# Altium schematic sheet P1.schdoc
size 297 x 209 mm; Symbol: Drawing-Symbol_A4; @Project Name: New Project_2025-09-22_16-04-54; @Page Count: 2; @Update Date: 2025-10-16; @Create Date: 2025-09-22; @Schematic Name: Schematic1; @Page No: 1; @Page Name: P1; Company: EasyEDA.com; Version: V1.0; Page Size: A4; @Create Time: 16:05:01; @Update Time: 22:39:59; Border: 1; Width: 1170; Height: 825; Region Start: 1; X Region Count: 6; Y Region Count: 4; Blade Width: 10; Title Block Position: 3; @Board Name: Board1; Device: Drawing-Symbol_A4
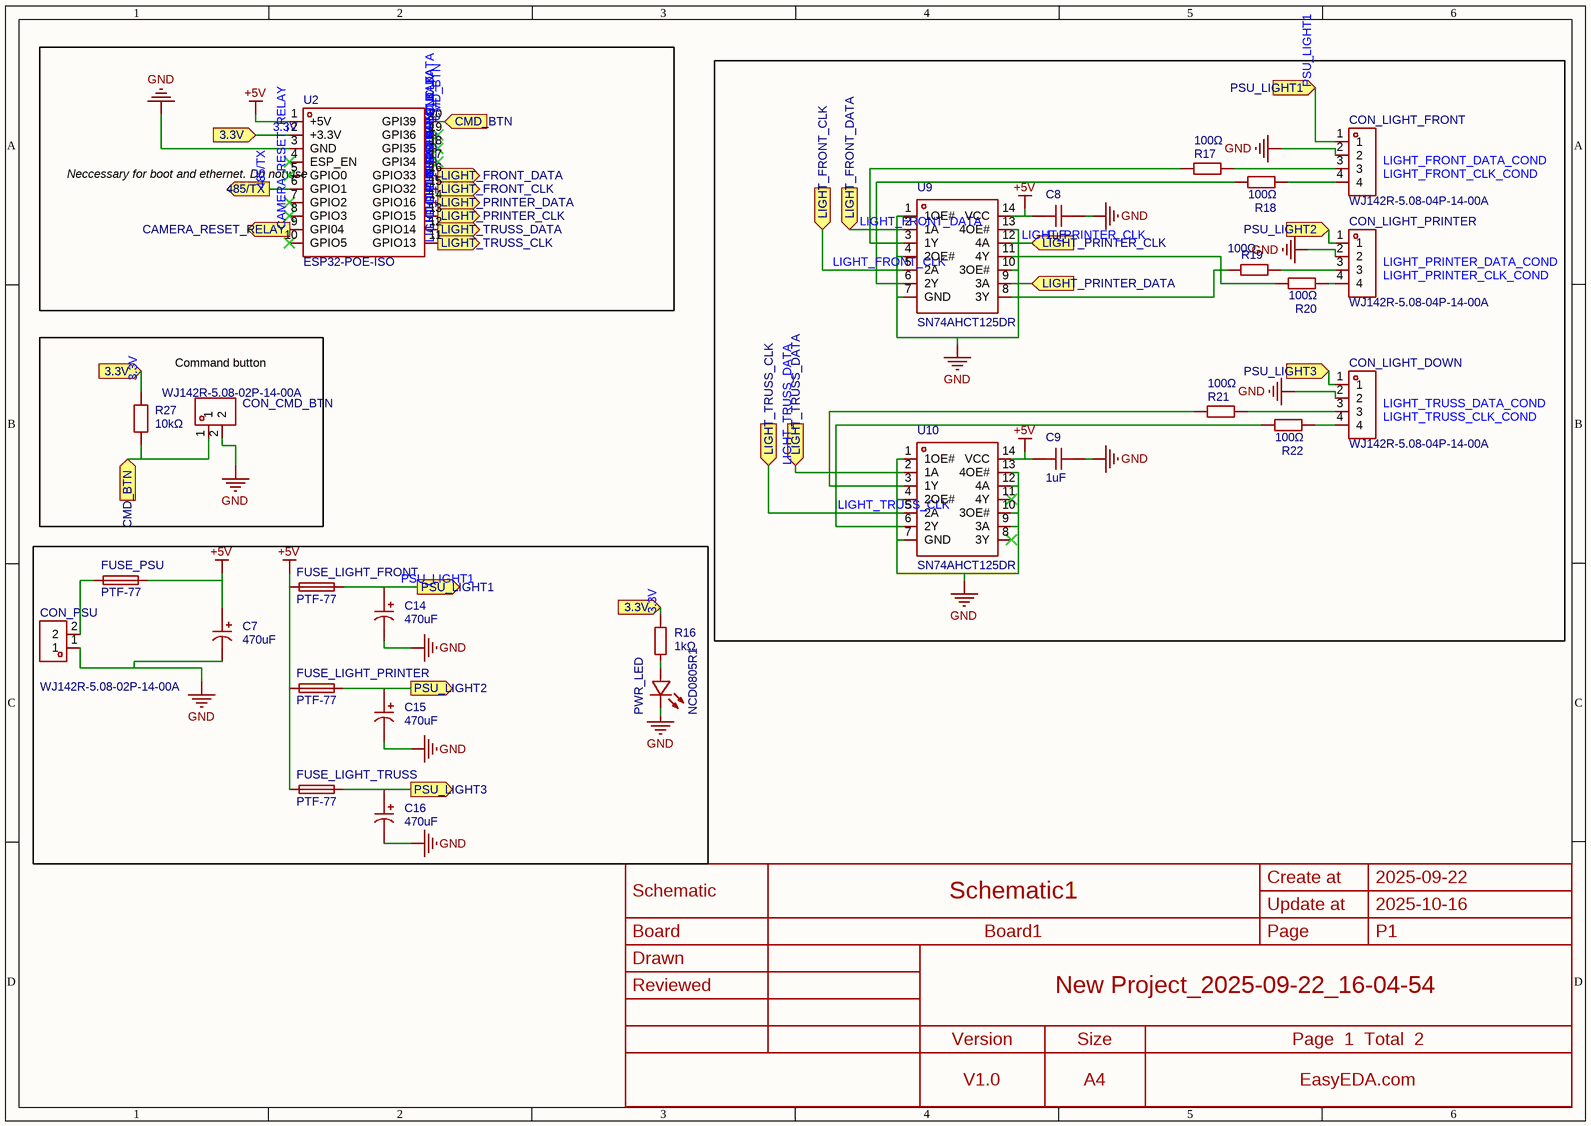
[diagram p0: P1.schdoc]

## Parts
C7  470uF  [CAP-TH_BD8.0-P3.50-D0.5-FD]
C8  1uF  [C0603]
C9  1uF  [C0603]
C14  470uF  [CAP-TH_BD8.0-P3.50-D0.5-FD]
C15  470uF  [CAP-TH_BD8.0-P3.50-D0.5-FD]
C16  470uF  [CAP-TH_BD8.0-P3.50-D0.5-FD]
CON_CMD_BTN  WJ142R-5.08-02P-14-00A  [CONN-TH_2P-P5.08_WJ142R-5.08-2P]
CON_LIGHT_DOWN  WJ142R-5.08-04P-14-00A  [CONN-TH_WJ142R-5.08-4P]
CON_LIGHT_FRONT  WJ142R-5.08-04P-14-00A  [CONN-TH_WJ142R-5.08-4P]
CON_LIGHT_PRINTER  WJ142R-5.08-04P-14-00A  [CONN-TH_WJ142R-5.08-4P]
CON_PSU  WJ142R-5.08-02P-14-00A  [CONN-TH_2P-P5.08_WJ142R-5.08-2P]
FUSE_LIGHT_FRONT  PTF-77  [FUSE-TH_L24.4-W9.4-P22.60]
FUSE_LIGHT_PRINTER  PTF-77  [FUSE-TH_L24.4-W9.4-P22.60]
FUSE_LIGHT_TRUSS  PTF-77  [FUSE-TH_L24.4-W9.4-P22.60]
FUSE_PSU  PTF-77  [FUSE-TH_L24.4-W9.4-P22.60]
PWR_LED  NCD0805R1  [LED0805-R-RD]
R16  1kΩ  [R0603]
R17  100Ω  [R0603]
R18  100Ω  [R0603]
R19  100Ω  [R0603]
R20  100Ω  [R0603]
R21  100Ω  [R0603]
R22  100Ω  [R0603]
R27  10kΩ  [R0603]
U2  ESP32-POE-ISO  [COMM-TH_20P-P2.54_ESP32-POE-ISO]
U9  SN74AHCT125DR  [SOIC-14_L8.7-W3.9-P1.27-LS6.0-BL]
U10  SN74AHCT125DR  [SOIC-14_L8.7-W3.9-P1.27-LS6.0-BL]

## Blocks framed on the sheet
Neccessary for boot and ethernet. Do not use: U2
Command button: CON_CMD_BTN R27

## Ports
3.3V (in), 485/TX (out), CAMERA_RESET_RELAY (out), CMD_BTN (in), LIGHT_FRONT_CLK (in), LIGHT_FRONT_CLK (out), LIGHT_FRONT_DATA (in), LIGHT_FRONT_DATA (out), LIGHT_PRINTER_CLK (in), LIGHT_PRINTER_CLK (out), LIGHT_PRINTER_DATA (in), LIGHT_PRINTER_DATA (out), LIGHT_TRUSS_CLK (in), LIGHT_TRUSS_CLK (out), LIGHT_TRUSS_DATA (in), LIGHT_TRUSS_DATA (out), PSU_LIGHT1 (in), PSU_LIGHT1 (out), PSU_LIGHT2 (in), PSU_LIGHT2 (out), PSU_LIGHT3 (in), PSU_LIGHT3 (out)

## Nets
+5V: C7.1 C8.1 C9.1 FUSE_LIGHT_FRONT.1 FUSE_LIGHT_PRINTER.1 FUSE_LIGHT_TRUSS.1 FUSE_PSU.2 U2.1(+5V) U9.14(VCC) U10.14(VCC)
GND: C7.2 C8.2 C9.2 C14.2 C15.2 C16.2 CON_CMD_BTN.2 CON_LIGHT_DOWN.2 CON_LIGHT_FRONT.2 CON_LIGHT_PRINTER.2 CON_PSU.1 PWR_LED.2(-) U2.3(GND) U9.1(1OE#) U9.4(2OE#) U9.7(GND) U9.10(3OE#) U9.13(4OE#) U10.1(1OE#) U10.4(2OE#) U10.7(GND) U10.9(3A) U10.10(3OE#) U10.12(4A) U10.13(4OE#)
3.3V: R16.2 R27.2 U2.2(+3.3V) ; port 3.3V
485/TX: U2.6(GPIO1) ; port 485/TX
CAMERA_RESET_RELAY: U2.9(GPI04) ; port CAMERA_RESET_RELAY
CMD_BTN: CON_CMD_BTN.1 R27.1 U2.20(GPI39) ; port CMD_BTN
LIGHT_FRONT_CLK: U2.15(GPIO32) U9.5(2A) ; port LIGHT_FRONT_CLK
LIGHT_FRONT_DATA: U2.16(GPIO33) U9.2(1A) ; port LIGHT_FRONT_DATA
LIGHT_PRINTER_CLK: U2.13(GPIO15) U9.12(4A) ; port LIGHT_PRINTER_CLK
LIGHT_PRINTER_DATA: U2.14(GPIO16) U9.9(3A) ; port LIGHT_PRINTER_DATA
LIGHT_TRUSS_CLK: U2.11(GPIO13) U10.5(2A) ; port LIGHT_TRUSS_CLK
LIGHT_TRUSS_DATA: U2.12(GPIO14) U10.2(1A) ; port LIGHT_TRUSS_DATA
PSU_LIGHT1: C14.1 CON_LIGHT_FRONT.1 FUSE_LIGHT_FRONT.2 ; port PSU_LIGHT1
PSU_LIGHT2: C15.1 CON_LIGHT_PRINTER.1 FUSE_LIGHT_PRINTER.2 ; port PSU_LIGHT2
PSU_LIGHT3: C16.1 CON_LIGHT_DOWN.1 FUSE_LIGHT_TRUSS.2 ; port PSU_LIGHT3
NetCON_LIGHT_DOWN_3: CON_LIGHT_DOWN.3 R21.2
NetCON_LIGHT_DOWN_4: CON_LIGHT_DOWN.4 R22.2
NetCON_LIGHT_FRONT_3: CON_LIGHT_FRONT.3 R17.2
NetCON_LIGHT_FRONT_4: CON_LIGHT_FRONT.4 R18.2
NetCON_LIGHT_PRINTER_3: CON_LIGHT_PRINTER.3 R19.2
NetCON_LIGHT_PRINTER_4: CON_LIGHT_PRINTER.4 R20.2
NetCON_PSU_2: CON_PSU.2 FUSE_PSU.1
NetPWR_LED_1: PWR_LED.1(+) R16.1
NetR17_1: R17.1 U9.3(1Y)
NetR18_1: R18.1 U9.6(2Y)
NetR19_1: R19.1 U9.8(3Y)
NetR20_1: R20.1 U9.11(4Y)
NetR21_1: R21.1 U10.3(1Y)
NetR22_1: R22.1 U10.6(2Y)

Not connected (* = marked no-connect by the designer): U2 4(ESP_EN)* 5(GPIO0)* 7(GPIO2)* 8(GPIO3)* 10(GPIO5)* 17(GPI34)* 18(GPI35)* 19(GPI36)*; U10 8(3Y)* 11(4Y)*

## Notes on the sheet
- Labels drawn without touching a wire or pin: LIGHT_FRONT_CLK_COND, LIGHT_FRONT_DATA_COND, LIGHT_PRINTER_CLK_COND, LIGHT_PRINTER_DATA_COND, LIGHT_TRUSS_CLK_COND, LIGHT_TRUSS_DATA_COND

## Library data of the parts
C7 C14-C16 = 25V470uF CD110: Capacitance:470uF Tolerance:±20% Tolerance:±20% Voltage Rating:25V Pin Spacing:3.5mm Diameter:8mm Height - Seated (Max):12mm Operating Temperature:-40℃~+105℃ Operating Temperature:-40℃~+105℃; Manufacturer: HRK(鸿瑞凯电子); Symbol: RVT1C471M0607; AddInBom: yes; ModelId: da67121c92c24fd188d878c9437c8745; ModelTransform: 314.96,315.3537,0,90,0,0,0,0,-196.85; Tolerance: ±20%; Voltage Rating: 25V; Pin Spacing: 3.5mm
C8 C9 = CL10A105KB8NNNC: Capacitance:1uF Tolerance:±10% Tolerance:±10% Voltage Rating:50V Temperature Coefficient:X5R; Manufacturer: SAMSUNG(三星); AddInBom: yes; ModelId: 624118aa3cc7497086c383c2d72e0852; ModelName: C0603_L1.6-W0.8-H0.8; ModelTransform: 62.992,31.496,0,0,0,0,0,0,0; Tolerance: ±10%; Voltage Rating: 50V; Temperature Coefficient: X5R
CON_CMD_BTN CON_PSU = WJ142R-5.08-02P-14-00A: Pitch:5.08mm Mounting Type:Through Hole Number of Pins:2P Number of PINs Per Row:2 Number of Rows:1 Current Rating:10A Voltage Rating (Max):300V Wire Gauge - AWG:14~22 Wire Gauge - mm2:1.5 Operating Temperature:-40℃~+105℃ Operating Temperature:-40℃~+105℃; Manufacturer: KANGNEX(康奈克斯电气); Symbol: KF250NH-3.5-2P; AddInBom: yes; ModelId: 9a502304c63443359925f49f0614e344; ModelTransform: 499.999,555.117,0,0,0,0,-52.166,58.858,-137.795; Pitch: 5.08mm; Number of PINs Per Row: 2; Current Rating: 10A; Voltage Rating (Max): 300V; Wire Gauge - AWG: 14~22; Wire Gauge - mm2: 1.5
CON_LIGHT_DOWN CON_LIGHT_FRONT CON_LIGHT_PRINTER = WJ142R-5.08-04P-14-00A: Pitch:5.08mm Mounting Type:Through Hole Number of Pins:4P Number of PINs Per Row:4 Number of Rows:1 Current Rating:10A Voltage Rating (Max):300V Wire Gauge - AWG:14~22 Wire Gauge - mm2:1.5 Operating Temperature:-40℃~+105℃ Operating Temperature:-40℃~+105℃; Manufacturer: KANGNEX(康奈克斯电气); Symbol: KF250NH-3.5-4P; AddInBom: yes; ModelId: e0ff7f97ea2949628ae5f69dd1e71b3b; ModelTransform: 899.9982,555.117,0,0,0,0,-49.606,59.055,-137.795; Pitch: 5.08mm; Number of PINs Per Row: 4; Current Rating: 10A; Voltage Rating (Max): 300V; Wire Gauge - AWG: 14~22; Wire Gauge - mm2: 1.5
FUSE_LIGHT_FRONT FUSE_LIGHT_PRINTER FUSE_LIGHT_TRUSS FUSE_PSU = PTF-77: Fuseholder Type:- Voltage Rating:250V Current Rating:10A Fuse Type:- Fuse Size:-; Manufacturer: XFCN(兴飞); AddInBom: yes; ModelId: bf7d7b0754cc4e26a98b4eb39c780e43; ModelName: FUSE-TH_L24.4-W9.4-H11.5-P22.60; ModelTransform: 960.628,370.078,0,0,0,0,0,0,-137.795; Voltage Rating: 250V; Current Rating: 10A
PWR_LED = NCD0805R1_C84256: Lamp Holder Type:- Emitted Color:Red Forward Voltage (VF):1.6V~2.6V Forward Voltage (VF):1.6V~2.6V Power Dissipation:65mW Forward Current:20mA Dominant Wavelength:615nm~630nm Dominant Wavelength:615nm~630nm Peak Wavelength:- Diode Configuration:独立二极管 Lens; Manufacturer: 国星光电; Symbol: FC-2012HRK-620D; AddInBom: yes; ModelId: 167045bb0eae412b9d5564860e113a91; ModelName: LED0805-RD; ModelTransform: 79.527,49.2125,0,0,0,0,0,0,0; Emitted Color: Red; Power Dissipation: 65mW; Forward Current: 20mA; Diode Configuration: 独立二极管; Lens Color: 无色透明透镜; Luminous Intensity: 67mcd~195mcd; Viewing Angle: 130°
R16 = 0603WAF1001T5E: Type:Thick Film Resistors Resistance:1kΩ Tolerance:±1% Tolerance:±1% Power(Watts): Overload Voltage (Max): Temperature Coefficient:±100ppm/℃ Temperature Coefficient:±100ppm/℃ Operating Temperature Range:-55℃~+155℃ Operating Temperature Range:-55℃~+155℃; Manufacturer: UNI-ROYAL(厚声); AddInBom: yes; ModelId: 112863783b5b41f1b5254f87eedc7932; ModelTransform: 31.8897,63.7794,0,90,0,0,0,0,0; Tolerance: ±1%
R17-R22 = 0603WAF1000T5E: Type:Thick Film Resistors Resistance: Tolerance:±1% Tolerance:±1% Power(Watts): Overload Voltage (Max): Temperature Coefficient:±200ppm/℃ Temperature Coefficient:±200ppm/℃ Operating Temperature Range:-55℃~+155℃ Operating Temperature Range:-55℃~+155℃; Manufacturer: UNI-ROYAL(厚声); AddInBom: yes; ModelId: 112863783b5b41f1b5254f87eedc7932; ModelTransform: 31.8897,63.7794,0,90,0,0,0,0,0; Tolerance: ±1%
R27 = 0603WAF1002T5E: Type:Thick Film Resistor Resistance:10kΩ Tolerance:±1% Tolerance:±1% Power(Watts):100mW Voltage-Supply(Max):75V Temperature Coefficient:±100ppm/℃ Temperature Coefficient:±100ppm/℃ Operating Temperature:-55℃~+155℃ Operating Temperature:-55℃~+155℃; Manufacturer: UNI-ROYAL(厚声); Symbol: FRC0603J103TS; AddInBom: yes; ModelId: 112863783b5b41f1b5254f87eedc7932; ModelTransform: 31.8897,63.7794,0,90,0,0,0,0,0; Tolerance: ±1%; Power(Watts): 100mW; Voltage-Supply(Max): 75V
U2 = ESP32-POE-ISO: Manufacturer: Olimex; AddInBom: yes
U9 U10 = SN74AHCT125DR: output type:Tri-State Voltage - Supply:4.5V~5.5V Voltage - Supply:4.5V~5.5V Number of Elements:4 Number of Bits per Element:1 Current - Output Low(IOL):8mA Current - Output High(IOH):8mA Logic Family:74AHCT Operating Temperature:-40℃~+85℃ Operating Temper; Manufacturer: TI(德州仪器); AddInBom: yes; ModelId: 4a4abff9a5634443a503282266e86697; ModelName: SOIC-14_L8.6-W3.9-H1.8-LS6.0-P1.27; ModelTransform: 338.583,236.22,0,0,0,0,0,-0.001,0; Number of Elements: 4; Number of Bits per Element: 1; Current - Output Low(IOL): 8mA; Logic Family: 74AHCT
